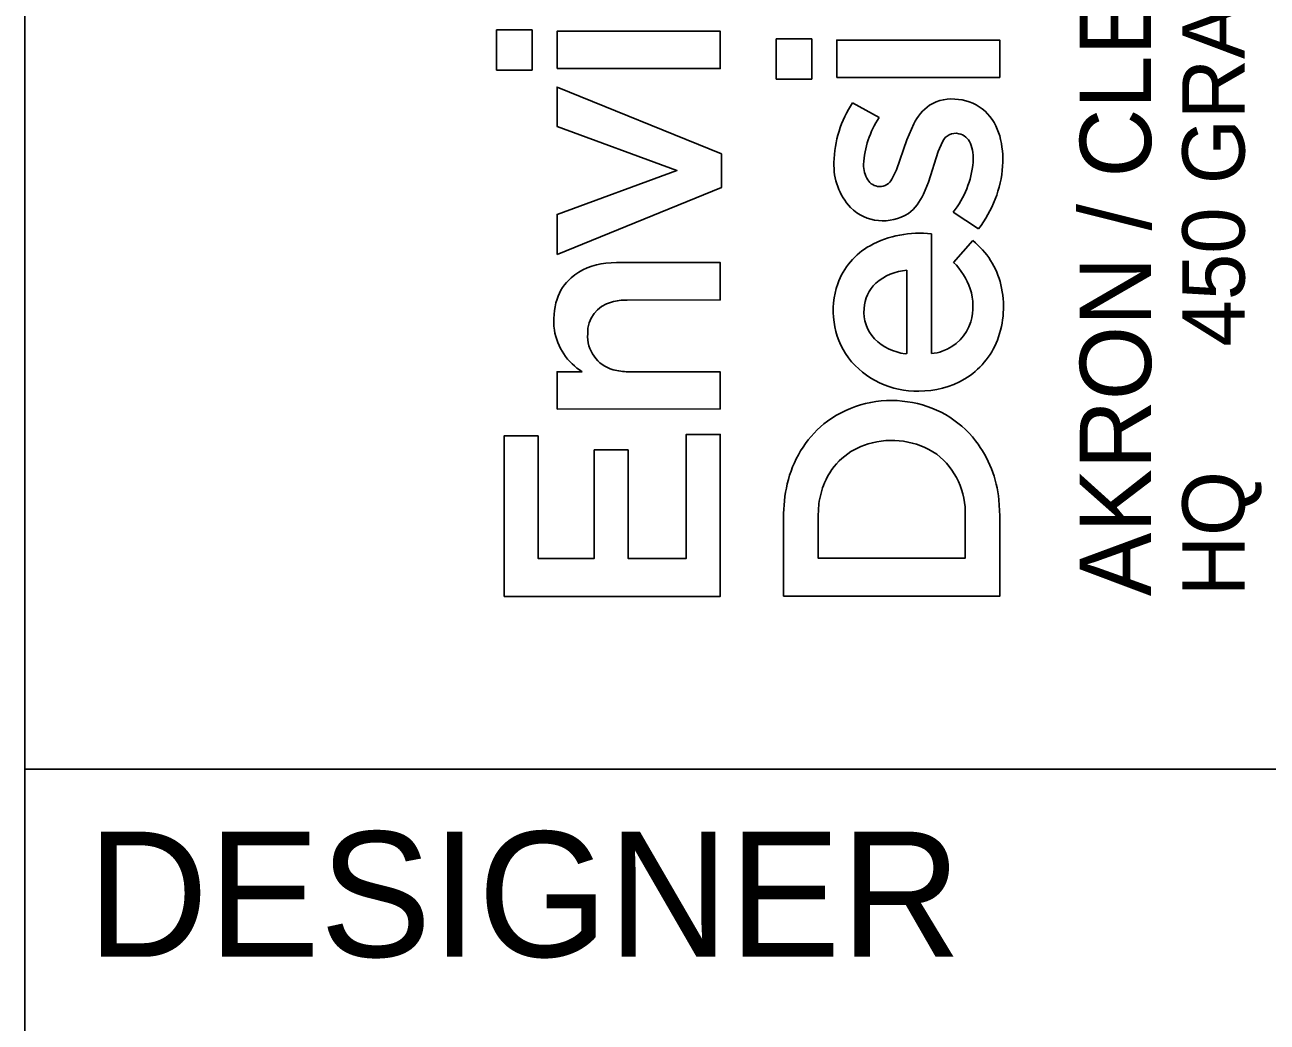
# Model space of a CAD drawing. Extents: x 0 to 70.6, y 0 to 31.9.
# Drawn here: x 32 to 32.993, y 2.798 to 3.594 of the extents above; entities that cross this region are included whole.
import ezdxf

# ---------------------------------------------------------------- set-up
doc = ezdxf.new("R2010")
doc.units = 0
doc.layers.add('GM_X_County', color=7, linetype='Continuous')
doc.layers.add('GM_X_Township', color=7, linetype='Continuous')

msp = doc.modelspace()

# ---------------------------------------------------------------- linework, layer by layer
at = {"layer": 'GM_X_County'}
for p, q in [((32, 0.5), (32, 21.5)), ((32, 3), (33.5, 3))]:
    msp.add_line(p, q, dxfattribs=at)
at = {"layer": 'GM_X_Township'}
for p, q in [((32.37705, 3.55818), (32.37705, 3.59026)), ((32.37705, 3.59026), (32.40543, 3.59026)), ((32.40543, 3.59026), (32.40543, 3.55818)), ((32.42542, 3.55942), (32.42542, 3.58928)), ((32.42542, 3.58928), (32.55571, 3.58928)), ((32.55571, 3.58928), (32.55571, 3.55942)), ((32.60051, 3.55111), (32.60051, 3.58319)), ((32.60051, 3.58319), (32.62889, 3.58319)), ((32.62889, 3.58319), (32.62889, 3.55111)), ((32.64888, 3.55234), (32.64888, 3.5822)), ((32.64888, 3.5822), (32.77917, 3.5822)), ((32.77917, 3.5822), (32.77917, 3.55234)), ((32.40543, 3.55818), (32.37705, 3.55818)), ((32.55571, 3.55942), (32.42542, 3.55942)), ((32.42542, 3.51327), (32.42542, 3.5446)), ((32.42542, 3.5446), (32.5567, 3.4913)), ((32.62889, 3.55111), (32.60051, 3.55111)), ((32.77917, 3.55234), (32.64888, 3.55234)), ((32.66151, 3.53207), (32.68268, 3.52025)), ((32.70483, 3.50258), (32.71036, 3.51526)), ((32.52117, 3.47798), (32.42542, 3.51327)), ((32.69675, 3.47868), (32.70483, 3.50258)), ((32.73342, 3.50101), (32.72985, 3.4933)), ((32.5567, 3.4913), (32.5567, 3.46441)), ((32.72985, 3.4933), (32.72213, 3.46882)), ((32.42542, 3.44294), (32.52117, 3.47798)), ((32.69299, 3.47117), (32.69675, 3.47868)), ((32.72213, 3.46882), (32.71822, 3.45921)), ((32.5567, 3.46441), (32.42542, 3.41086)), ((32.42542, 3.41086), (32.42542, 3.44294)), ((32.76214, 3.43141), (32.74198, 3.44469)), ((32.72453, 3.42747), (32.72463, 3.33195)), ((32.74228, 3.40465), (32.75768, 3.422)), ((32.46439, 3.40397), (32.47289, 3.40443)), ((32.47289, 3.40443), (32.55571, 3.40443)), ((32.55571, 3.40443), (32.55571, 3.37465)), ((32.70489, 3.33182), (32.70489, 3.39834)), ((32.55571, 3.37465), (32.4814, 3.37457)), ((32.70361, 3.33165), (32.70489, 3.33182)), ((32.42542, 3.31728), (32.44552, 3.31733)), ((32.42542, 3.28747), (32.42542, 3.31728)), ((32.48222, 3.31733), (32.55569, 3.31733)), ((32.55569, 3.31733), (32.55571, 3.28756)), ((32.55571, 3.28756), (32.42542, 3.28747)), ((32.52857, 3.16827), (32.52857, 3.26722)), ((32.52857, 3.26722), (32.55571, 3.26722)), ((32.55571, 3.26722), (32.55571, 3.13791)), ((32.38298, 3.13791), (32.38298, 3.26598)), ((32.38298, 3.26598), (32.41012, 3.26598)), ((32.41012, 3.26598), (32.41012, 3.16827)), ((32.45503, 3.16827), (32.45503, 3.25488)), ((32.45503, 3.25488), (32.48218, 3.25488)), ((32.48218, 3.25488), (32.48218, 3.16827)), ((32.63465, 3.21178), (32.63407, 3.2023)), ((32.77847, 3.21497), (32.77917, 3.2021)), ((32.60643, 3.13799), (32.60644, 3.204)), ((32.63407, 3.2023), (32.63407, 3.16838)), ((32.75149, 3.16834), (32.75153, 3.20239)), ((32.77917, 3.2021), (32.77917, 3.138)), ((32.41012, 3.16827), (32.45503, 3.16827)), ((32.48218, 3.16827), (32.52857, 3.16827)), ((32.63407, 3.16838), (32.75149, 3.16834)), ((32.55571, 3.13791), (32.38298, 3.13791)), ((32.77917, 3.138), (32.60643, 3.13799))]:
    msp.add_line(p, q, dxfattribs=at)
for points in [[(32.37705, 3.55818), (32.37705, 3.59026), (32.40543, 3.59026), (32.40543, 3.55818)], [(32.42542, 3.55942), (32.42542, 3.58928), (32.55571, 3.58928), (32.55571, 3.55942)], [(32.60051, 3.55111), (32.60051, 3.58319), (32.62889, 3.58319), (32.62889, 3.55111)], [(32.64888, 3.55234), (32.64888, 3.5822), (32.77917, 3.5822), (32.77917, 3.55234)], [(32.42542, 3.41086), (32.42542, 3.44294), (32.52117, 3.47798), (32.42542, 3.51327), (32.42542, 3.5446), (32.5567, 3.4913), (32.5567, 3.46441)], [(32.38298, 3.13791), (32.38298, 3.26598), (32.41012, 3.26598), (32.41012, 3.16827), (32.45503, 3.16827), (32.45503, 3.25488), (32.48218, 3.25488), (32.48218, 3.16827), (32.52857, 3.16827), (32.52857, 3.26722), (32.55571, 3.26722), (32.55571, 3.13791)]]:
    msp.add_lwpolyline(points, close=True, dxfattribs=at)
for points in [[(32.66151, 3.53207), (32.68268, 3.52025)], [(32.69299, 3.47117), (32.69675, 3.47868), (32.70483, 3.50258), (32.71036, 3.51526)], [(32.73342, 3.50101), (32.72985, 3.4933), (32.72213, 3.46882), (32.71822, 3.45921)], [(32.76214, 3.43141), (32.74198, 3.44469)], [(32.72453, 3.42747), (32.72463, 3.33195)], [(32.74228, 3.40465), (32.75768, 3.422)], [(32.46439, 3.40397), (32.47289, 3.40443), (32.55571, 3.40443), (32.55571, 3.37465), (32.4814, 3.37457)], [(32.70361, 3.33165), (32.70489, 3.33182), (32.70489, 3.39834)], [(32.42542, 3.28747), (32.42542, 3.31728), (32.44552, 3.31733)], [(32.48222, 3.31733), (32.55569, 3.31733), (32.55571, 3.28756), (32.42542, 3.28747)], [(32.77847, 3.21497), (32.77917, 3.2021), (32.77917, 3.138), (32.60643, 3.13799)], [(32.63465, 3.21178), (32.63407, 3.2023), (32.63407, 3.16838), (32.75149, 3.16834), (32.75153, 3.20239)], [(32.60643, 3.13799), (32.60644, 3.204)]]:
    msp.add_lwpolyline(points, dxfattribs=at)
for centre, radius, start, end in [((32.7406, 3.5026), 0.03263, 80.17192, 122.51969), ((32.7406, 3.5026), 0.03263, 80.17192, 122.51969), ((32.74278, 3.49824), 0.03667, 47.79344, 84.68918), ((32.74278, 3.49824), 0.03667, 47.79344, 84.68918), ((32.73636, 3.48258), 0.08973, 146.53104, 178.7571), ((32.73636, 3.48258), 0.08973, 146.53104, 178.7571), ((32.74661, 3.49713), 0.04053, 125.51182, 153.41595), ((32.74661, 3.49713), 0.04053, 125.51182, 153.41595), ((32.73788, 3.4946), 0.04267, 14.9966, 46.20632), ((32.73788, 3.4946), 0.04267, 14.9966, 46.20632), ((32.74519, 3.4789), 0.07495, 146.51121, 176.91007), ((32.74519, 3.4789), 0.07495, 146.51121, 176.91007), ((32.74384, 3.49631), 0.01143, 76.66094, 155.7053), ((32.74384, 3.49631), 0.01143, 76.66094, 155.7053), ((32.74397, 3.49511), 0.01256, 21.5098, 78.52618), ((32.74397, 3.49511), 0.01256, 21.5098, 78.52618), ((32.71044, 3.48674), 0.07121, 355.83062, 15.39138), ((32.71044, 3.48674), 0.07121, 355.83062, 15.39138), ((32.72592, 3.48766), 0.03209, 354.57264, 22.06805), ((32.72592, 3.48766), 0.03209, 354.57264, 22.06805), ((32.69666, 3.48238), 0.05005, 177.53659, 222.79318), ((32.69666, 3.48238), 0.05005, 177.53659, 222.79318), ((32.6931, 3.48233), 0.02276, 178.47474, 211.08679), ((32.6931, 3.48233), 0.02276, 178.47474, 211.08679), ((32.68248, 3.49149), 0.0757, 321.81101, 354.79685), ((32.68248, 3.49149), 0.0757, 321.81101, 354.79685), ((32.68952, 3.4882), 0.09219, 321.9777, 355.87384), ((32.68952, 3.4882), 0.09219, 321.9777, 355.87384), ((32.68331, 3.4767), 0.01148, 212.23676, 268.37769), ((32.68331, 3.4767), 0.01148, 212.23676, 268.37769), ((32.68342, 3.47589), 0.01067, 267.71603, 333.73375), ((32.68342, 3.47589), 0.01067, 267.71603, 333.73375), ((32.68098, 3.4758), 0.04077, 308.08772, 335.98736), ((32.68098, 3.4758), 0.04077, 308.08772, 335.98736), ((32.68599, 3.47535), 0.0375, 225.98539, 302.47965), ((32.68599, 3.47535), 0.0375, 225.98539, 302.47965), ((32.7152, 3.34414), 0.08384, 83.61499, 118.28755), ((32.7152, 3.34414), 0.08384, 83.61499, 118.28755), ((32.70239, 3.36906), 0.05583, 118.83082, 160.62438), ((32.70239, 3.36906), 0.05583, 118.83082, 160.62438), ((32.71744, 3.37167), 0.06443, 13.53365, 51.36148), ((32.71744, 3.37167), 0.06443, 13.53365, 51.36148), ((32.46871, 3.35428), 0.04988, 94.96958, 130.22249), ((32.46871, 3.35428), 0.04988, 94.96958, 130.22249), ((32.70785, 3.35609), 0.04235, 94.00805, 130.88169), ((32.70785, 3.35609), 0.04235, 94.00805, 130.88169), ((32.70378, 3.36556), 0.05486, 19.03571, 45.44059), ((32.70378, 3.36556), 0.05486, 19.03571, 45.44059), ((32.46348, 3.36263), 0.04015, 132.22192, 161.68183), ((32.46348, 3.36263), 0.04015, 132.22192, 161.68183), ((32.71041, 3.36612), 0.06437, 160.52012, 215.78311), ((32.71041, 3.36612), 0.06437, 160.52012, 215.78311), ((32.70048, 3.36628), 0.02985, 132.98507, 177.179), ((32.70048, 3.36628), 0.02985, 132.98507, 177.179), ((32.70635, 3.36921), 0.07579, 339.3542, 13.37853), ((32.70635, 3.36921), 0.07579, 339.3542, 13.37853), ((32.71069, 3.3697), 0.047, 344.60586, 17.007), ((32.71069, 3.3697), 0.047, 344.60586, 17.007), ((32.47872, 3.35819), 0.05601, 162.27355, 187.79185), ((32.47872, 3.35819), 0.05601, 162.27355, 187.79185), ((32.47482, 3.34867), 0.02498, 103.68646, 182.21874), ((32.47482, 3.34867), 0.02498, 103.68646, 182.21874), ((32.48108, 3.32856), 0.04601, 89.60494, 105.3284), ((32.48108, 3.32856), 0.04601, 89.60494, 105.3284), ((32.7017, 3.36503), 0.03115, 175.00126, 223.28301), ((32.7017, 3.36503), 0.03115, 175.00126, 223.28301), ((32.7224, 3.36715), 0.03504, 288.00773, 343.55078), ((32.7224, 3.36715), 0.03504, 288.00773, 343.55078), ((32.47026, 3.35802), 0.04762, 188.96199, 238.70369), ((32.47026, 3.35802), 0.04762, 188.96199, 238.70369), ((32.47735, 3.34558), 0.02756, 175.58538, 255.14386), ((32.47735, 3.34558), 0.02756, 175.58538, 255.14386), ((32.70891, 3.37363), 0.04231, 225.06188, 262.79738), ((32.70891, 3.37363), 0.04231, 225.06188, 262.79738), ((32.71894, 3.3652), 0.0626, 300.94269, 338.73225), ((32.71894, 3.3652), 0.0626, 300.94269, 338.73225), ((32.71253, 3.37054), 0.06872, 217.74516, 271.65431), ((32.71253, 3.37054), 0.06872, 217.74516, 271.65431), ((32.72474, 3.35216), 0.02021, 269.7003, 294.8711), ((32.72474, 3.35216), 0.02021, 269.7003, 294.8711), ((32.48183, 3.35948), 0.04215, 254.09162, 270.52835), ((32.48183, 3.35948), 0.04215, 254.09162, 270.52835), ((32.71549, 3.37241), 0.07056, 269.20477, 300.33412), ((32.71549, 3.37241), 0.07056, 269.20477, 300.33412), ((32.69229, 3.20792), 0.08641, 81.19402, 125.99844), ((32.69229, 3.20792), 0.08641, 81.19402, 125.99844), ((32.69458, 3.21132), 0.08272, 37.85208, 82.40204), ((32.69458, 3.21132), 0.08272, 37.85208, 82.40204), ((32.69387, 3.20893), 0.08654, 127.23621, 165.14796), ((32.69387, 3.20893), 0.08654, 127.23621, 165.14796), ((32.68893, 3.20782), 0.05398, 106.18808, 157.38609), ((32.68893, 3.20782), 0.05398, 106.18808, 157.38609), ((32.69279, 3.19862), 0.06389, 55.67272, 107.20935), ((32.69279, 3.19862), 0.06389, 55.67272, 107.20935), ((32.68586, 3.20567), 0.09308, 5.73329, 37.30396), ((32.68586, 3.20567), 0.09308, 5.73329, 37.30396), ((32.69291, 3.20499), 0.05867, 357.46616, 52.26647), ((32.69291, 3.20499), 0.05867, 357.46616, 52.26647), ((32.71426, 3.20281), 0.10783, 164.7861, 179.37039), ((32.71426, 3.20281), 0.10783, 164.7861, 179.37039), ((32.69829, 3.20389), 0.06412, 157.35705, 172.92755), ((32.69829, 3.20389), 0.06412, 157.35705, 172.92755)]:
    msp.add_arc(centre, radius, start, end, dxfattribs=at)

# ---------------------------------------------------------------- texts
for s, height, p in [('450 GRANT ST., AKRON, OH  44311', 0.0498462, (32.97489, 3.33738)), ('AKRON / CLEVELAND / COLUMBUS', 0.056969, (32.90012, 3.138)), ('HQ ', 0.049846, (32.97489, 3.138))]:
    msp.add_text(s, height=height, rotation=90, dxfattribs=at).set_placement(p)
msp.add_text('DESIGNER', height=0.1, dxfattribs=at).set_placement((32.05, 2.85))

doc.saveas('drawing.dxf')
